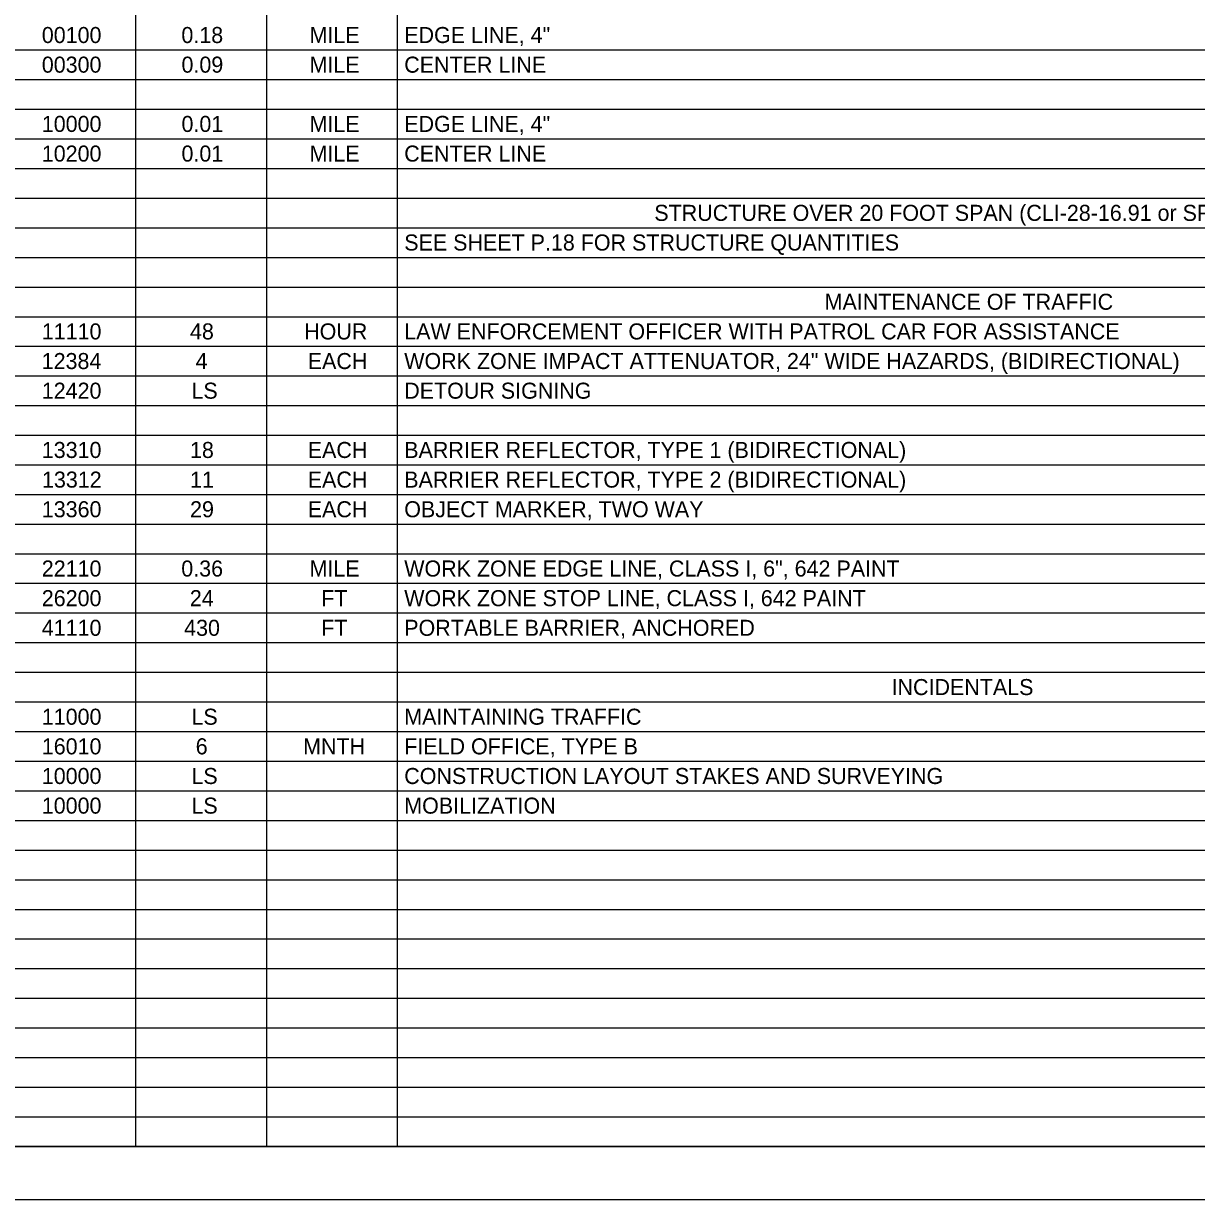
# Model space of a CAD drawing. Extents: x 0 to 34, y 0 to 22.
# Drawn here: x 16.98 to 28.05, y 0 to 11.11 of the extents above; entities that cross this region are included whole.
import ezdxf

# ---------------------------------------------------------------- set-up
doc = ezdxf.new("R2010")
doc.units = 0
for name, color, linetype in [('SH_Border', 7, 'Continuous'), ('SH_Cut_Line', 7, 'Continuous'), ('SH_Text', 7, 'Continuous')]:
    doc.layers.add(name, color=color, linetype=linetype)

msp = doc.modelspace()

# ---------------------------------------------------------------- linework, layer by layer
at = {"layer": 'SH_Border'}
msp.add_lwpolyline([(1.5, 21.5), (33.5, 21.5), (33.5, 0.5), (1.5, 0.5)], close=True, dxfattribs=at)
at = {"layer": 'SH_Cut_Line'}
msp.add_lwpolyline([(0, 0), (34, 0), (34, 22), (0, 22)], close=True, dxfattribs=at)
at = {"layer": 'SH_Text'}
for p, q in [((18.036, 21.5), (18.036, 0.501)), ((19.271, 21.5), (19.271, 0.501)), ((20.506, 21.5), (20.506, 0.501)), ((1.5, 10.86), (32.002, 10.86)), ((1.5, 10.58), (32.002, 10.58)), ((1.5, 10.3), (32.002, 10.3)), ((1.5, 10.02), (32.002, 10.02)), ((1.5, 9.74), (32.002, 9.74)), ((1.5, 9.46), (32.002, 9.46)), ((1.5, 9.18), (32.002, 9.18)), ((1.5, 8.9), (32.002, 8.9)), ((1.5, 8.62), (32.002, 8.62)), ((1.5, 8.34), (32.002, 8.34)), ((1.5, 8.06), (32.002, 8.06)), ((1.5, 7.78), (32.002, 7.78)), ((1.5, 7.5), (32.002, 7.5)), ((1.5, 7.221), (32.002, 7.221)), ((1.5, 6.941), (32.002, 6.941)), ((1.5, 6.661), (32.002, 6.661)), ((1.5, 6.381), (32.002, 6.381)), ((1.5, 6.101), (32.002, 6.101)), ((1.5, 5.821), (32.002, 5.821)), ((1.5, 5.541), (32.002, 5.541)), ((1.5, 5.261), (32.002, 5.261)), ((1.5, 4.981), (32.002, 4.981)), ((1.5, 4.701), (32.002, 4.701)), ((1.5, 4.421), (32.002, 4.421)), ((1.5, 4.141), (32.002, 4.141)), ((1.5, 3.861), (32.002, 3.861)), ((1.5, 3.581), (32.002, 3.581)), ((1.5, 3.301), (32.002, 3.301)), ((1.5, 3.021), (32.002, 3.021)), ((1.5, 2.741), (32.002, 2.741)), ((1.5, 2.461), (32.002, 2.461)), ((1.5, 2.181), (32.002, 2.181)), ((1.5, 1.901), (32.002, 1.901)), ((1.5, 1.621), (32.002, 1.621)), ((1.5, 1.341), (32.002, 1.341)), ((1.5, 1.061), (32.002, 1.061)), ((1.5, 0.781), (32.002, 0.781)), ((1.5, 0.501), (32.002, 0.501))]:
    msp.add_line(p, q, dxfattribs=at)

# ---------------------------------------------------------------- texts
for s, height, p in [('00100', 0.1515, (17.15, 10.925)), ('0.18', 0.1515, (18.468, 10.925)), ('MILE', 0.1515, (19.678, 10.925)), ('EDGE LINE, 4"', 0.15152, (20.572, 10.925)), ('00300', 0.1515, (17.15, 10.645)), ('0.09', 0.1515, (18.469, 10.645)), ('MILE', 0.1515, (19.678, 10.645)), ('CENTER LINE', 0.15152, (20.572, 10.645)), ('10000', 0.1515, (17.15, 10.085)), ('0.01', 0.1515, (18.469, 10.085)), ('MILE', 0.1515, (19.678, 10.085)), ('EDGE LINE, 4"', 0.15152, (20.572, 10.085)), ('10200', 0.1515, (17.15, 9.805)), ('0.01', 0.1515, (18.469, 9.805)), ('MILE', 0.1515, (19.678, 9.805)), ('CENTER LINE', 0.15152, (20.572, 9.805)), ('STRUCTURE OVER 20 FOOT SPAN (CLI-28-16.91 or SFN 1400746)', 0.15152, (22.933, 9.245)), ('SEE SHEET P.18 FOR STRUCTURE QUANTITIES', 0.15152, (20.572, 8.965)), ('MAINTENANCE OF TRAFFIC', 0.15152, (24.541, 8.405)), ('11110', 0.1515, (17.15, 8.125)), ('48', 0.1515, (18.549, 8.125)), ('HOUR', 0.1515, (19.627, 8.125)), ('LAW ENFORCEMENT OFFICER WITH PATROL CAR FOR ASSISTANCE', 0.15152, (20.572, 8.125)), ('WORK ZONE IMPACT ATTENUATOR, 24" WIDE HAZARDS, (BIDIRECTIONAL)', 0.15152, (20.572, 7.845)), ('12384', 0.1515, (17.149, 7.845)), ('4', 0.152, (18.602, 7.845)), ('EACH', 0.1515, (19.661, 7.845)), ('12420', 0.1515, (17.15, 7.565)), ('LS', 0.1515, (18.563, 7.565)), ('DETOUR SIGNING', 0.15152, (20.572, 7.565)), ('13310', 0.1515, (17.15, 7.005)), ('18', 0.1515, (18.549, 7.005)), ('EACH', 0.1515, (19.661, 7.005)), ('BARRIER REFLECTOR, TYPE 1 (BIDIRECTIONAL)', 0.15152, (20.572, 7.005)), ('13312', 0.1515, (17.152, 6.725)), ('11', 0.1515, (18.55, 6.725)), ('EACH', 0.1515, (19.661, 6.725)), ('BARRIER REFLECTOR, TYPE 2 (BIDIRECTIONAL)', 0.15152, (20.572, 6.725)), ('13360', 0.1515, (17.15, 6.445)), ('29', 0.1515, (18.55, 6.445)), ('EACH', 0.1515, (19.661, 6.445)), ('OBJECT MARKER, TWO WAY', 0.15152, (20.572, 6.445)), ('22110', 0.1515, (17.15, 5.885)), ('0.36', 0.1515, (18.467, 5.885)), ('MILE', 0.1515, (19.678, 5.885)), ('WORK ZONE EDGE LINE, CLASS I, 6", 642 PAINT', 0.15152, (20.572, 5.885)), ('26200', 0.1515, (17.15, 5.605)), ('24', 0.1515, (18.548, 5.605)), ('FT', 0.1515, (19.788, 5.605)), ('WORK ZONE STOP LINE, CLASS I, 642 PAINT', 0.15152, (20.572, 5.605)), ('41110', 0.1515, (17.15, 5.325)), ('430', 0.1515, (18.494, 5.325)), ('FT', 0.1515, (19.788, 5.325)), ('PORTABLE BARRIER, ANCHORED', 0.15152, (20.572, 5.325)), ('INCIDENTALS', 0.15152, (25.173, 4.765)), ('11000', 0.1515, (17.15, 4.485)), ('LS', 0.1515, (18.563, 4.485)), ('MAINTAINING TRAFFIC', 0.15152, (20.572, 4.485)), ('16010', 0.1515, (17.15, 4.205)), ('6', 0.152, (18.603, 4.205)), ('MNTH', 0.1515, (19.617, 4.205)), ('FIELD OFFICE, TYPE B', 0.15152, (20.572, 4.205)), ('10000', 0.1515, (17.15, 3.925)), ('LS', 0.1515, (18.563, 3.925)), ('CONSTRUCTION LAYOUT STAKES AND SURVEYING', 0.15152, (20.572, 3.925)), ('10000', 0.1515, (17.15, 3.645)), ('LS', 0.1515, (18.563, 3.645)), ('MOBILIZATION', 0.15152, (20.572, 3.645))]:
    msp.add_text(s, height=height, dxfattribs=at).set_placement(p)

doc.saveas('drawing.dxf')
